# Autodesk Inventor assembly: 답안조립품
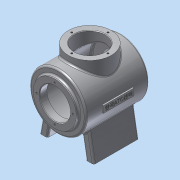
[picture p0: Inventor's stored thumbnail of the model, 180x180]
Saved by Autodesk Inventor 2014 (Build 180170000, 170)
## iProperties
Created: 2015-01
Part Number: 답안조립품
Document SubType Name: Assembly
Designer: user
Author: user
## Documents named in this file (2)
- C:\Users\user\Desktop\450105V1037\답안조립품.iam
- C:\Users\user\Desktop\450105V1037\본체.ipt
